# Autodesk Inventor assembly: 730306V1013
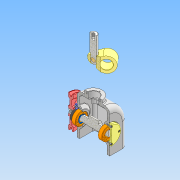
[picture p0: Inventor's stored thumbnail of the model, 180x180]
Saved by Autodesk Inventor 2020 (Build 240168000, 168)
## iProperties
Created: 2023-03
Part Number: 730306V1013
Document SubType Name: Assembly
Designer: user
Author: user
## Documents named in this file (17)
- C:\Users\user\Desktop\730306V1013\730306V1013.iam
- C:\Users\user\Desktop\730306V1013\본체.ipt
- C:\Users\user\Desktop\730306V1013\고정핀.ipt
- C:\Users\user\Desktop\730306V1013\링크.ipt
- C:\Users\user\Desktop\730306V1013\슬라이더.ipt
- C:\Users\user\Desktop\730306V1013\편심축.ipt
- C:\Users\user\Desktop\730306V1013\베어링 6205.ipt
- 베어링 6205.ipt
- C:\Users\user\Desktop\730306V1013\뒷커버.ipt
- C:\Users\user\Desktop\730306V1013\볼트 M4 x 12.ipt
- C:\Users\user\Desktop\730306V1013\멈춤링 25 x 1.2.ipt
- 멈춤링 25 x 1.2.ipt
- C:\Users\user\Desktop\730306V1013\앞커버.ipt
- C:\Users\user\Desktop\730306V1013\오일실 25 40 8.ipt
- 오일실 25 40 8.ipt
- C:\Users\user\Desktop\730306V1013\V-벨트풀리.ipt
- C:\Users\user\Desktop\730306V1013\키 6x6x14.ipt
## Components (2 placed, 2 different names)
1. 고정핀:1
2. V-벨트풀리:1
